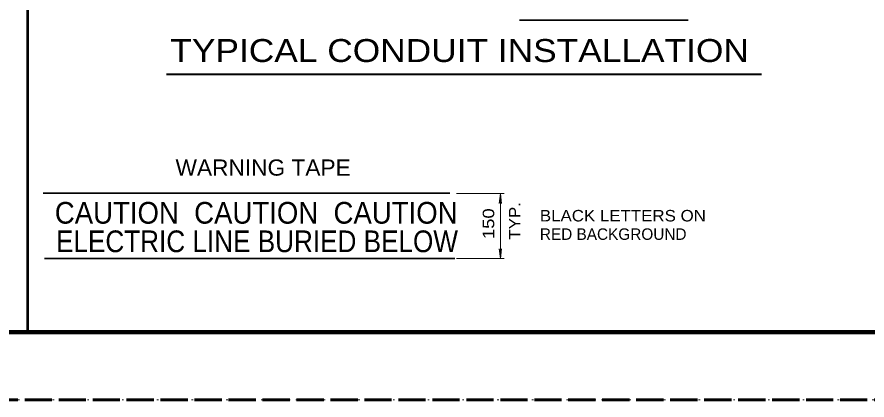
# Model space of a CAD drawing. Extents: x 312583 to 312854, y 144419 to 144597.
# Drawn here: x 312741.4 to 312797.7, y 144418.6 to 144443.9 of the extents above; entities that cross this region are included whole.
import ezdxf
from ezdxf.enums import TextEntityAlignment as Align

# ---------------------------------------------------------------- set-up
doc = ezdxf.new("R2010")
doc.units = 0
doc.header["$LTSCALE"] = 0.3
doc.linetypes.add('DOTTED', pattern=[1.5, 0.3, -1.2])
doc.linetypes.add('LONG_DASHED', pattern=[7.5, 6, -1.5])
for name, color, linetype, lineweight in [('1', 7, 'Continuous', 40), ('2', 7, 'Continuous', 13), ('63', 7, 'DOTTED', 13)]:
    doc.layers.add(name, color=color, linetype=linetype, lineweight=lineweight)

msp = doc.modelspace()

# ---------------------------------------------------------------- linework, layer by layer
at = {"layer": '1', "lineweight": 53}
msp.add_line((312742.1369, 144540.9979), (312742.1369, 144423.0846), dxfattribs=at)
at = {"layer": '1'}
msp.add_line((312751.3312, 144440.1506), (312790.7348, 144440.1506), dxfattribs=at)
at = {"layer": '1', "lineweight": 158}
msp.add_line((312616.5, 144423.0846), (312849, 144423.0846), dxfattribs=at)
at = {"layer": '1', "linetype": 'LONG_DASHED', "lineweight": 60}
msp.add_line((312851.75, 144418.5846), (312583.526, 144418.5846), dxfattribs=at)
at = {"layer": '2', "lineweight": 35}
for p, q in [((312774.7088, 144443.7279), (312785.8868, 144443.7279)), ((312743.1607, 144432.265), (312770.1014, 144432.265)), ((312743.268, 144427.9486), (312770.431, 144427.9486))]:
    msp.add_line(p, q, dxfattribs=at)
at = {"layer": '2'}
for p, q in [((312770.5384, 144432.2496), (312773.7124, 144432.2496)), ((312773.4509, 144432.2496), (312773.3666, 144431.598)), ((312773.3666, 144431.598), (312773.4509, 144431.805)), ((312773.4509, 144432.2496), (312773.5276, 144431.598)), ((312773.4509, 144432.2496), (312773.4509, 144427.9486)), ((312773.5276, 144431.598), (312773.4509, 144431.805)), ((312773.3666, 144428.6003), (312773.4509, 144428.3933)), ((312773.4509, 144427.9486), (312773.3666, 144428.6003)), ((312773.5276, 144428.6003), (312773.4509, 144428.3933)), ((312773.4509, 144427.9486), (312773.5276, 144428.6003)), ((312770.5384, 144427.9486), (312773.7124, 144427.9486))]:
    msp.add_line(p, q, dxfattribs=at)
at = {"layer": '63'}
msp.add_lwpolyline([(312601.2, 144418.5846), (312853.5, 144418.5846), (312853.5, 144596.7846)], dxfattribs=at)

# ---------------------------------------------------------------- texts
at = {"layer": '2'}
for s, height, width, p in [('TYPICAL CONDUIT INSTALLATION', 1.52, 1.15, (312770.7515, 144440.9573)), ('WARNING TAPE', 1.07, 1.05, (312757.7392, 144433.436)), ('CAUTION  CAUTION  CAUTION', 1.437, 0.95, (312757.2789, 144430.2563)), ('ELECTRIC LINE BURIED BELOW', 1.437, 0.9, (312757.3325, 144428.3703))]:
    msp.add_text(s, height=height, dxfattribs=dict(at, width=width)).set_placement(p, align=Align.CENTER)
for s, width, p in [('150 ', 1.2, (312773.0425, 144429.2364)), ('TYP.', 1.1, (312774.7789, 144429.201))]:
    msp.add_text(s, height=0.76, rotation=90, dxfattribs=dict(at, width=width)).set_placement(p)
at = {"layer": '2', "width": 1.1}
msp.add_text('BLACK LETTERS ON', height=0.76, dxfattribs=at).set_placement((312776.0659, 144430.4047))
at = {"layer": '2'}
msp.add_text('RED BACKGROUND', height=0.76, dxfattribs=at).set_placement((312776.0659, 144429.1847))

doc.saveas('drawing.dxf')
